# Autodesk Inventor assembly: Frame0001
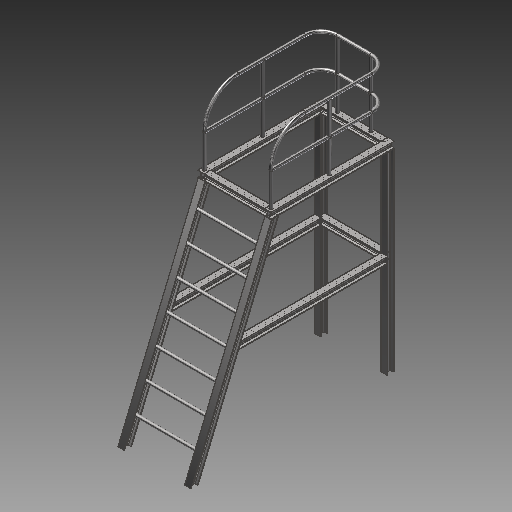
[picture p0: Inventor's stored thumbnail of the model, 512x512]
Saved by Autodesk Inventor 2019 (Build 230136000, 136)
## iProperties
Created: 2018-07
Part Number: Frame0001
Material: Générique
Document SubType Name: Assembly
Designer: Fabian Perrée
Mass: 566701 g
Surface Area: 202439 cm^2
Volume: 72191.3 cm^3
Density: 7.85 g/cm^3
_FrameDoc: Frame Assembly
_Version: 15.0.0
Author: Fabian Perrée
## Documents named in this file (38)
- C:\Users\Fabian\Google Drive\04_CAO\01_Inventor\01_Fichiers_exercice_Inventor\02_A_traiter\Frame Generator\Frame\Frame0001.iam
- C:\Users\Fabian\Google Drive\04_CAO\01_Inventor\01_Fichiers_exercice_Inventor\02_A_traiter\Frame Generator\Frame\Skeleton0001.ipt
- C:\Users\Fabian\Google Drive\04_CAO\01_Inventor\01_Fichiers_exercice_Inventor\02_A_traiter\Frame Generator\Frame\ISO SC 100 00000001.ipt
- ISO SC 100 00000001.ipt
- C:\Users\Fabian\Google Drive\04_CAO\01_Inventor\01_Fichiers_exercice_Inventor\02_A_traiter\Frame Generator\Frame\ISO SC 100 00000002.ipt
- ISO SC 100 00000002.ipt
- C:\Users\Fabian\Google Drive\04_CAO\01_Inventor\01_Fichiers_exercice_Inventor\02_A_traiter\Frame Generator\Frame\ISO SC 100 00000003.ipt
- ISO SC 100 00000003.ipt
- C:\Users\Fabian\Google Drive\04_CAO\01_Inventor\01_Fichiers_exercice_Inventor\02_A_traiter\Frame Generator\Frame\ISO SC 100 00000006.ipt
- ISO SC 100 00000006.ipt
- C:\Users\Fabian\Google Drive\04_CAO\01_Inventor\01_Fichiers_exercice_Inventor\02_A_traiter\Frame Generator\Frame\ISO SC 100 00000008.ipt
- ISO SC 100 00000008.ipt
- C:\Users\Fabian\Google Drive\04_CAO\01_Inventor\01_Fichiers_exercice_Inventor\02_A_traiter\Frame Generator\Frame\ISO 48.3x2.0 00000010.ipt
- ISO 48.3x2.0 00000010.ipt
- C:\Users\Fabian\Google Drive\04_CAO\01_Inventor\01_Fichiers_exercice_Inventor\02_A_traiter\Frame Generator\Frame\ISO 48.3x2.0 00000011.ipt
- ISO 48.3x2.0 00000011.ipt
- C:\Users\Fabian\Google Drive\04_CAO\01_Inventor\01_Fichiers_exercice_Inventor\02_A_traiter\Frame Generator\Frame\ISO 48.3x2.0 00000012.ipt
- ISO 48.3x2.0 00000012.ipt
- C:\Users\Fabian\Google Drive\04_CAO\01_Inventor\01_Fichiers_exercice_Inventor\02_A_traiter\Frame Generator\Frame\ISO 48.3x2.0 00000013.ipt
- ISO 48.3x2.0 00000013.ipt
- C:\Users\Fabian\Google Drive\04_CAO\01_Inventor\01_Fichiers_exercice_Inventor\02_A_traiter\Frame Generator\Frame\ISO 48.3x2.0 00000014.ipt
- ISO 48.3x2.0 00000014.ipt
- C:\Users\Fabian\Google Drive\04_CAO\01_Inventor\01_Fichiers_exercice_Inventor\02_A_traiter\Frame Generator\Frame\ISO 48.3x2.0 00000015.ipt
- ISO 48.3x2.0 00000015.ipt
- C:\Users\Fabian\Google Drive\04_CAO\01_Inventor\01_Fichiers_exercice_Inventor\02_A_traiter\Frame Generator\Frame\ISO 48.3x2.0 00000016.ipt
- ISO 48.3x2.0 00000016.ipt
- C:\Users\Fabian\Google Drive\04_CAO\01_Inventor\01_Fichiers_exercice_Inventor\02_A_traiter\Frame Generator\Frame\ISO SC 100 00000018.ipt
- ISO SC 100 00000018.ipt
- C:\Users\Fabian\Google Drive\04_CAO\01_Inventor\01_Fichiers_exercice_Inventor\02_A_traiter\Frame Generator\Frame\ISO SC 100 00000019.ipt
- ISO SC 100 00000019.ipt
- C:\Users\Fabian\Google Drive\04_CAO\01_Inventor\01_Fichiers_exercice_Inventor\02_A_traiter\Frame Generator\Frame\ISO 48.3x2.0 00000021.ipt
- ISO 48.3x2.0 00000021.ipt
- C:\Users\Fabian\Google Drive\04_CAO\01_Inventor\01_Fichiers_exercice_Inventor\02_A_traiter\Frame Generator\Frame\ISO 48.3x2.0 00000022.ipt
- ISO 48.3x2.0 00000022.ipt
- C:\Users\Fabian\Google Drive\04_CAO\01_Inventor\01_Fichiers_exercice_Inventor\02_A_traiter\Frame Generator\Frame\ISO 48.3x2.0 00000027.ipt
- ISO 48.3x2.0 00000027.ipt
- C:\Users\Fabian\Google Drive\04_CAO\01_Inventor\01_Fichiers_exercice_Inventor\02_A_traiter\Frame Generator\Frame\ISO 48.3x2.0 00000028.ipt
- ISO 48.3x2.0 00000028.ipt
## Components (30 placed, 19 different names)
1. Modèle de référence de l'ossature
2. ISO SC 100 00000008:1
3. ISO 48.3x2.0 00000010:1
4. ISO 48.3x2.0 00000011:1
5. ISO 48.3x2.0 00000012:1
6. ISO 48.3x2.0 00000013:1
7. ISO 48.3x2.0 00000014:1
8. ISO 48.3x2.0 00000015:1
9. ISO 48.3x2.0 00000016:1
10. ISO SC 100 00000019:1
11. ISO 48.3x2.0 00000021:1
12. ISO 48.3x2.0 00000022:1
13. ISO 48.3x2.0 00000027:1
14. ISO 48.3x2.0 00000027:2
15. ISO 48.3x2.0 00000027:3
16. ISO 48.3x2.0 00000027:4
17. ISO 48.3x2.0 00000028:1
18. ISO 48.3x2.0 00000028:2
19. ISO 48.3x2.0 00000028:3
20. ISO 48.3x2.0 00000028:4
21. ISO SC 100 00000006:1
22. ISO SC 100 00000006:2
23. ISO SC 100 00000018:1
24. ISO SC 100 00000018:2
25. ISO SC 100 00000001:1
26. ISO SC 100 00000001:2
27. ISO SC 100 00000002:1
28. ISO SC 100 00000002:2
29. ISO SC 100 00000003:1
30. ISO SC 100 00000003:2
